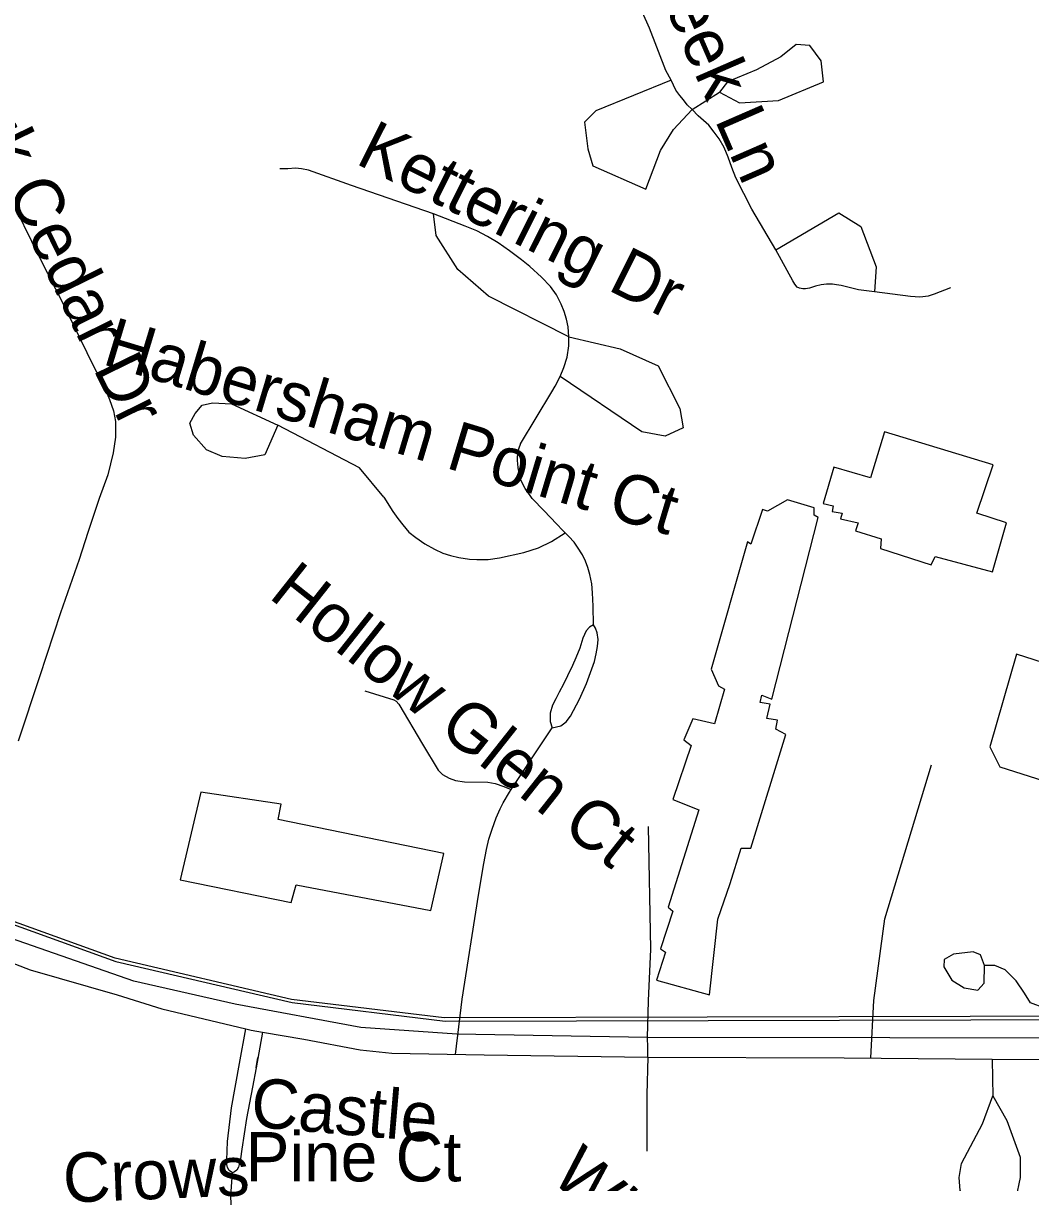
# Model space of a CAD drawing. Extents: x 1383679 to 1536984, y 460658 to 651027.
# Drawn here: x 1442107 to 1444051, y 491747 to 493982 of the extents above; entities that cross this region are included whole.
import ezdxf

# ---------------------------------------------------------------- set-up
doc = ezdxf.new("R2010")
doc.units = 0
for name, color, linetype in [('Default', 7, 'Continuous'), ('Exist Boundary Political City Limit New', 7, 'Continuous'), ('Exist Cultural Warehouse Building Footprint', 7, 'Continuous'), ('Exist Hydrographic Misc Water Feature', 7, 'Continuous'), ('Exist Road Non-System Type 51', 7, 'Continuous'), ('Exist Road Non-System Type 51 Label', 7, 'Continuous'), ('Exist Road Primary NC UnDivided 4 Lane Attributed', 7, 'Continuous'), ('Map Preparation Boundary City Limit Buffer Line', 7, 'Continuous')]:
    doc.layers.add(name, color=color, linetype=linetype)

msp = doc.modelspace()

# ---------------------------------------------------------------- linework, layer by layer
at = {"layer": 'Default'}
msp.add_lwpolyline([(1440354.1, 492088.6), (1440370.5, 492375.2), (1440374.9, 492488.3), (1440732.6, 492438.9), (1440805.2, 492692.5), (1441438.4, 492479.3), (1442286.2, 492173.4), (1442626, 492094.2), (1442921, 492058.5), (1444442.5, 492062.3), (1444699.5, 492218.9), (1445438.8, 492725.9), (1445436.1, 492731.4)], dxfattribs=at)
at = {"layer": 'Exist Boundary Political City Limit New'}
for points in [[(1445436.1, 492731.4), (1444697.9, 492225.1), (1444440.9, 492068.5), (1442919.4, 492064.6), (1442624.4, 492100.4), (1442284.6, 492179.6), (1441436.8, 492485.4), (1440803.6, 492698.6), (1440731, 492445.1), (1440373.2, 492494.5), (1440368.9, 492381.4), (1440352.4, 492094.7), (1440354.1, 492088.6)], [(1440354.1, 492088.6), (1440370.5, 492375.2), (1440374.9, 492488.3), (1440732.6, 492438.9), (1440805.2, 492692.5), (1441438.4, 492479.3), (1442286.2, 492173.4), (1442626, 492094.2), (1442921, 492058.5), (1444442.5, 492062.3), (1444699.5, 492218.9), (1445438.8, 492725.9), (1445436.1, 492731.4)]]:
    msp.add_lwpolyline(points, dxfattribs=at)
at = {"layer": 'Exist Cultural Warehouse Building Footprint'}
for points in [[(1443768.6, 493194.4), (1443741.4, 493105.9), (1443671, 493126.1), (1443650.2, 493056.3), (1443669.4, 493051.6), (1443667.8, 493040.7), (1443687, 493037.6), (1443683.8, 493026.8), (1443717.4, 493019), (1443712.6, 493003.5), (1443762.2, 492987.9), (1443760.6, 492969.3), (1443858.2, 492938.3), (1443866.2, 492953.8), (1443976.7, 492924.3), (1444003.9, 493019), (1443946.3, 493037.6), (1443978.3, 493130.8), (1443768.6, 493194.4)], [(1443328.5, 492137.2), (1443430.9, 492109.2), (1443446.9, 492255.2), (1443470.9, 492323.5), (1443491.7, 492391.8), (1443510.9, 492391.8), (1443578.2, 492610.7), (1443559, 492621.5), (1443562.2, 492638.6), (1443541.4, 492641.7), (1443547.8, 492669.7), (1443528.6, 492672.8), (1443531.8, 492686.8), (1443551, 492679), (1443640.6, 493029.1), (1443632.6, 493033.7), (1443632.6, 493047.7), (1443581.4, 493063.2), (1443543, 493041.5), (1443533.4, 493044.6), (1443510.9, 492977.8), (1443504.5, 492982.5), (1443434.1, 492737.2), (1443448.5, 492704.6), (1443459.7, 492698.4), (1443440.5, 492631.6), (1443398.9, 492641), (1443381.3, 492600.6), (1443395.7, 492589.7), (1443360.5, 492485.7), (1443410.1, 492465.5), (1443350.9, 492278.4), (1443360.5, 492270.7), (1443336.5, 492197.7), (1443346.1, 492191.5), (1443328.5, 492137.2)], [(1444023.1, 492765.9), (1443971.9, 492587.4), (1443991.1, 492548.6), (1444162.3, 492494.2), (1444191.1, 492514.4), (1444245.6, 492694.5), (1444023.1, 492765.9)], [(1442449.8, 492499.7), (1442409.8, 492330.5), (1442624.3, 492287), (1442633.9, 492321.1), (1442893.2, 492271.5), (1442918.8, 492381.7), (1442598.7, 492446.9), (1442605.1, 492476.4), (1442449.8, 492499.7)]]:
    msp.add_lwpolyline(points, dxfattribs=at)
at = {"layer": 'Exist Hydrographic Misc Water Feature'}
for points in [[(1443961.2, 492165.5), (1443953.6, 492186.2), (1443939.7, 492192.2), (1443901.5, 492187.2), (1443883.4, 492176.9), (1443883.1, 492163), (1443898.6, 492137.2), (1443922.3, 492122.8), (1443948.3, 492118.2), (1443960.6, 492131.9), (1443961.2, 492165.5)], [(1444379, 492036.5), (1444339.2, 492052.8), (1444303.5, 492067.5), (1444269.7, 492078), (1444233.7, 492078.8), (1444189.6, 492075.5), (1444151.5, 492072.2), (1444115.7, 492081.1), (1444077.7, 492083.5), (1444049.9, 492093.9), (1444038.3, 492112.2), (1444022.6, 492136.4), (1444001, 492157.3), (1443981.2, 492165.9), (1443961.2, 492165.5)]]:
    msp.add_lwpolyline(points, dxfattribs=at)
at = {"layer": 'Exist Road Non-System Type 51'}
for p, q in [((1442941, 491994.3), (1442953.8, 492100.9)), ((1443311.1, 492026.6), (1443313.3, 492097.6)), ((1443741.9, 491987.5), (1443747.8, 492098.1)), ((1442524.7, 491976.7), (1442536.7, 492043.7)), ((1443311.7, 492007.4), (1443311.1, 492026.6)), ((1443312.3, 491988.9), (1443310.1, 491917.2)), ((1443312.3, 491988.9), (1443311.7, 492007.4)), ((1443310.1, 491917.2), (1443310.3, 491807.8))]:
    msp.add_line(p, q, dxfattribs=at)
for points in [[(1443895.7, 493471.9), (1443864.3, 493459.7), (1443852.7, 493456.2), (1443842.3, 493454.6), (1443836.3, 493454.2), (1443818.6, 493455.2), (1443749.1, 493464), (1443718.4, 493468), (1443702.9, 493472.2), (1443692.3, 493474.5), (1443684.8, 493476.4), (1443675.9, 493477.8), (1443668.2, 493478.9), (1443656.6, 493478.9), (1443646.2, 493477.6), (1443635.4, 493474.9), (1443623.8, 493471.6), (1443616.1, 493470.1), (1443611.2, 493470.1), (1443604.5, 493471.2), (1443600.2, 493473.4), (1443595.2, 493478.9), (1443591.6, 493485.5), (1443559.1, 493545), (1443512.4, 493623.7), (1443481.5, 493684.1), (1443474, 493703.8), (1443466.9, 493724), (1443459.5, 493742.2), (1443449.7, 493759), (1443439.6, 493772.3), (1443429.4, 493785.6), (1443409.1, 493803.5), (1443397.6, 493815.5), (1443388.1, 493824.8), (1443381, 493834.2), (1443373.4, 493842.5), (1443366.3, 493853.3), (1443356.7, 493872.3), (1443346.8, 493890.8), (1443315.1, 493972.4), (1443277.2, 494057.7)], [(1443397.6, 493815.5), (1443450.1, 493848.9), (1443489, 493828.6), (1443563.8, 493833.3), (1443651, 493869.1), (1443646.3, 493909.7), (1443624.5, 493939.3), (1443598, 493940.8), (1443568.4, 493917.5), (1443521.7, 493892.5), (1443465.7, 493869.1), (1443450.1, 493848.9)], [(1443356.7, 493872.3), (1443211.8, 493813.1), (1443190, 493791.2), (1443196.2, 493739.8), (1443205.6, 493707.1), (1443308.4, 493661.9), (1443336.4, 493736.7), (1443361.3, 493777.2), (1443397.6, 493815.5)], [(1443152.5, 492999.8), (1443148.1, 493004.1), (1443135.8, 493017.1), (1443111.8, 493041.9), (1443089.2, 493066), (1443086.2, 493069.9), (1443083.5, 493073.6), (1443079.3, 493079.5), (1443075.6, 493085.3), (1443072.5, 493090.7), (1443070.2, 493095.3), (1443068, 493100.1), (1443065.8, 493106.2), (1443064.4, 493111.6), (1443063, 493118.5), (1443061.9, 493125.1), (1443061.1, 493132.6), (1443060.7, 493139.2), (1443060.7, 493145.5), (1443061, 493151.2), (1443062, 493157.9), (1443063.6, 493163.6), (1443066.2, 493170.3), (1443066.6, 493171.5), (1443127, 493271.3), (1443133.2, 493282.4), (1443143.1, 493301.1), (1443149.7, 493318.3), (1443156.4, 493338.3), (1443159.6, 493360), (1443159.6, 493377.6), (1443158.5, 493396.9), (1443155.1, 493411.3), (1443150.8, 493426.3), (1443144.6, 493440.5), (1443135.8, 493458.6), (1443124.4, 493474.5), (1443106.8, 493492.3), (1443084.4, 493512.9), (1443068.3, 493526.2), (1443045.3, 493543.4), (1443023, 493558.7), (1443002.8, 493570.9), (1442981.9, 493581.6), (1442959.6, 493591.1), (1442898.8, 493614.8), (1442740.7, 493669.5), (1442657.3, 493699.1), (1442644.2, 493701.7), (1442632.4, 493702.4), (1442617.8, 493701.7), (1442601.9, 493701.1)], [(1442077.5, 493654.9), (1442139, 493530.4), (1442184.8, 493439.6), (1442241.6, 493323.3), (1442263.3, 493281.9), (1442273.9, 493256.8), (1442281.2, 493234.8), (1442285.1, 493214.2), (1442285.3, 493184.1), (1442280.5, 493153.6), (1442270.2, 493111.4), (1442253.8, 493066), (1442231.8, 493000.1), (1442214.9, 492948.3), (1442179, 492845.5), (1442138.6, 492721.9), (1442097.7, 492598.2)], [(1443159.6, 493377.6), (1443004.7, 493455.9), (1442945.5, 493507.3), (1442903.5, 493572.8), (1442898.8, 493614.8)], [(1443559.1, 493545), (1443680.6, 493616.7), (1443722.6, 493590.2), (1443752.2, 493512.3), (1443749.1, 493464)], [(1443159.6, 493377.6), (1443258.5, 493354.6), (1443331.7, 493321.9), (1443373.8, 493239.3), (1443380, 493201.9), (1443345.7, 493186.3), (1443300.6, 493194.1), (1443143.1, 493301.1)], [(1442802.8, 493068.7), (1442755.8, 493125.3), (1442598.6, 493207.3), (1442573, 493150.1), (1442535.4, 493143.2), (1442491, 493146.6), (1442461, 493159.5), (1442435.4, 493187.7), (1442428.6, 493210.8), (1442438.8, 493229.6), (1442452.5, 493245.8), (1442472.2, 493250.1), (1442508.9, 493248.4), (1442598.6, 493207.3)], [(1442802.8, 493068.7), (1442820.2, 493040.8), (1442829.9, 493027.5), (1442839.5, 493014.8), (1442850.9, 493001.3), (1442864.6, 492990.7), (1442881.8, 492978.2), (1442900.3, 492967.9), (1442916.9, 492960.2), (1442931.7, 492955.8), (1442947.7, 492952.3), (1442967.8, 492949.2), (1442981.9, 492948.1), (1443003.8, 492948.3), (1443026, 492951.4), (1443072.9, 492961.8), (1443100.9, 492971), (1443126.1, 492982.8), (1443152.5, 492999.8)], [(1443206.9, 492822.4), (1443206.5, 492858.6), (1443205.9, 492870.9), (1443205.5, 492883.9), (1443203.7, 492901.6), (1443200.2, 492919.3), (1443196.4, 492932.7), (1443191.6, 492945.2), (1443185.9, 492957), (1443176.4, 492972.2), (1443169.6, 492981.4), (1443159.7, 492992.7), (1443152.5, 492999.8)], [(1443206.9, 492822.4), (1443199.3, 492817.7), (1443193.1, 492810.9), (1443186.5, 492796.9), (1443180.6, 492777.5), (1443173.1, 492758.6), (1443166.8, 492744.1), (1443157.1, 492724.1), (1443149.6, 492708.2), (1443141.1, 492692.6), (1443134.3, 492679.7), (1443128.1, 492667.6), (1443123.9, 492652), (1443123.9, 492636.2), (1443127.7, 492623.9)], [(1443127.7, 492623.9), (1443143.9, 492627.6), (1443154.3, 492635.1), (1443162.9, 492646.3), (1443180.2, 492679), (1443193.5, 492709.5), (1443204.1, 492737.5), (1443209, 492751.6), (1443212.6, 492766.3), (1443214.7, 492780.3), (1443216, 492794.2), (1443214.5, 492807.2), (1443211.2, 492815.7), (1443206.9, 492822.4)], [(1442766, 492694.9), (1442821.8, 492677.9), (1442826.4, 492675.2), (1442831.8, 492669.1), (1442877.3, 492592.3), (1442907.8, 492542.2), (1442916.1, 492534.1), (1442928.8, 492526.6), (1442941.2, 492522.5), (1442958.1, 492519.8), (1443003.5, 492519.1), (1443017.7, 492516.4), (1443034.1, 492511), (1443048.5, 492504.8)], [(1443048.5, 492504.8), (1443058.4, 492520.3), (1443099.3, 492581.6), (1443127.7, 492623.9)], [(1443747.8, 492098.1), (1443769.2, 492255.3), (1443859.1, 492552.3)], [(1442953.8, 492100.9), (1442985.4, 492301.2), (1442995.7, 492362.4), (1443000.7, 492389.1), (1443005.5, 492409.1), (1443011.7, 492428.7), (1443019.4, 492450.2), (1443027.2, 492467.4), (1443033.2, 492479), (1443045.3, 492499.9), (1443048.5, 492504.8)], [(1443313.3, 492097.6), (1443317.5, 492197.2), (1443313.2, 492433.9)], [(1442568.8, 492037.4), (1442556.3, 491968.2), (1442559.9, 491988.2)], [(1442510.9, 491765.8), (1442504.8, 491770.7), (1442501.5, 491776.4), (1442500.1, 491782.3), (1442500.1, 491790.7), (1442501.5, 491826.6), (1442509.2, 491891), (1442524.7, 491976.7)], [(1442556.3, 491968.2), (1442549.6, 491931.4), (1442537.8, 491870.5), (1442529.2, 491811.8), (1442526.3, 491792.8), (1442524.5, 491784.7), (1442522.3, 491776.6), (1442519.2, 491771.3), (1442514.9, 491767.6), (1442510.9, 491765.8)], [(1443976.3, 491985.4), (1443976.5, 491947.5), (1443977.6, 491914.7)], [(1443977.6, 491914.7), (1444004.6, 491867), (1444030.3, 491796.4), (1444030.3, 491756.9), (1444021.7, 491717.4), (1444002.5, 491702.9), (1443963.9, 491692.5), (1443934, 491705), (1443914.7, 491732), (1443912.6, 491756.9), (1443916.8, 491783.9), (1443957.5, 491860.7), (1443977.6, 491914.7)], [(1442520.1, 491580.9), (1442519.7, 491584.3), (1442514, 491642.1), (1442510.9, 491673.9), (1442509.4, 491692.2), (1442508.1, 491707.1), (1442507.4, 491720.1), (1442508.1, 491730.9), (1442510.9, 491765.8)]]:
    msp.add_lwpolyline(points, dxfattribs=at)
at = {"layer": 'Exist Road Primary NC UnDivided 4 Lane Attributed'}
for points in [[(1451375.5, 491065.7), (1451176.9, 491273.3), (1451016.4, 491407.7), (1450878.3, 491495), (1450727.6, 491571.2), (1450522.5, 491631.9), (1448821.1, 491963.1), (1448663.7, 491989.9), (1448374.3, 492021.1), (1446210.8, 492023.2), (1445181.3, 492024.4), (1443311.1, 492026.6), (1442943.4, 492033), (1442758.7, 492046.1), (1442516.1, 492090.9), (1442320.7, 492135.6), (1441928.9, 492271.9), (1440818.3, 492661.4), (1440612.8, 492709), (1440461.4, 492729.2)], [(1441995.2, 492205.7), (1442120.9, 492157.1), (1442288.6, 492109.4), (1442374.5, 492082.2), (1442536.7, 492043.7), (1442546.8, 492041.3), (1442568.8, 492037.4), (1442648.5, 492023.7), (1442756.9, 492002.8), (1442818.3, 491996.4), (1442996.2, 491993.4), (1443312.3, 491988.9), (1443690.4, 491987.9), (1443976.3, 491985.4), (1444257.9, 491983)]]:
    msp.add_lwpolyline(points, dxfattribs=at)
at = {"layer": 'Map Preparation Boundary City Limit Buffer Line'}
for points in [[(1445436.1, 492731.4), (1444697.9, 492225.1), (1444440.9, 492068.5), (1442919.4, 492064.6), (1442624.4, 492100.4), (1442284.6, 492179.6), (1441436.8, 492485.4), (1440803.6, 492698.6), (1440731, 492445.1), (1440373.2, 492494.5), (1440368.9, 492381.4), (1440352.4, 492094.7), (1440354.1, 492088.6)], [(1440354.1, 492088.6), (1440370.5, 492375.2), (1440374.9, 492488.3), (1440732.6, 492438.9), (1440805.2, 492692.5), (1441438.4, 492479.3), (1442286.2, 492173.4), (1442626, 492094.2), (1442921, 492058.5), (1444442.5, 492062.3), (1444699.5, 492218.9), (1445438.8, 492725.9), (1445436.1, 492731.4)], [(1440354.1, 492088.6), (1440370.5, 492375.2), (1440374.9, 492488.3), (1440732.6, 492438.9), (1440805.2, 492692.5), (1441438.4, 492479.3), (1442286.2, 492173.4), (1442626, 492094.2), (1442921, 492058.5), (1444442.5, 492062.3), (1444699.5, 492218.9), (1445438.8, 492725.9), (1445436.1, 492731.4)]]:
    msp.add_lwpolyline(points, dxfattribs=at)

# ---------------------------------------------------------------- texts
at = {"layer": 'Exist Road Non-System Type 51 Label'}
for s, rotation, p in [('Plum Creek Ln', 293.5239, (1443161.4, 494437)), ('Park Cedar Dr', 296.0296, (1441944, 493925.4)), ('Kettering Dr', 333.3883, (1442745.9, 493712.7)), ('Habersham Point Ct', 343.2099, (1442257.3, 493325.5)), ('Hollow Glen Ct', 321.6317, (1442578.5, 492875.8)), ('Castle', 355.1017, (1442543.9, 491855.3)), ('Pine Ct', 0.0008, (1442536, 491749.5)), ('Willo-', 317.5186, (1443122.5, 491754.6)), ('Crows', 2.2914, (1442185.7, 491708.4))]:
    msp.add_text(s, height=95, rotation=rotation, dxfattribs=at).set_placement(p)

doc.saveas('drawing.dxf')
